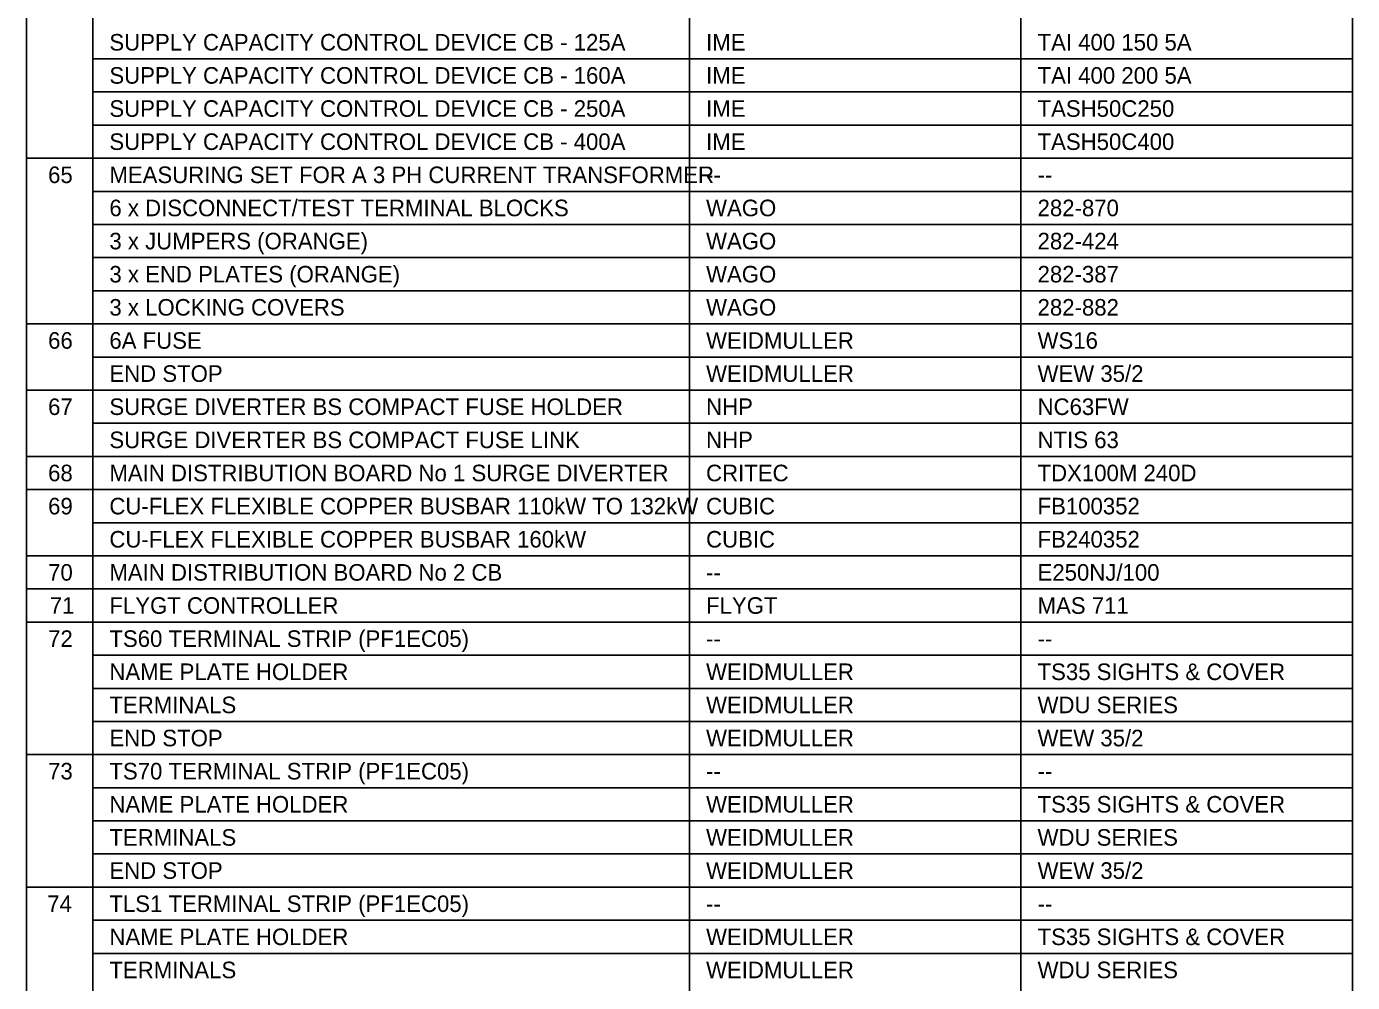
# Model space of a CAD drawing. Extents: x 841 to 1682, y 0 to 594.
# Drawn here: x 1340 to 1540, y 155.6 to 299.9 of the extents above; entities that cross this region are included whole.
import ezdxf

# ---------------------------------------------------------------- set-up
doc = ezdxf.new("R2010")
doc.units = 0
doc.layers.add('Level 1', color=7, linetype='Continuous')

msp = doc.modelspace()

# ---------------------------------------------------------------- linework, layer by layer
at = {"layer": 'Level 1'}
for p, q in [((1340, 568.5), (1340, 75)), ((1540, 75), (1540, 568.5)), ((1350, 558.75), (1350, 75)), ((1440, 558.75), (1440, 75)), ((1490, 558.75), (1490, 75)), ((1350, 295), (1540, 295)), ((1350, 290), (1540, 290)), ((1350, 285), (1540, 285)), ((1340, 280), (1540, 280)), ((1350, 275), (1540, 275)), ((1350, 270), (1540, 270)), ((1350, 265), (1540, 265)), ((1350, 260), (1540, 260)), ((1340, 255), (1540, 255)), ((1350, 250), (1540, 250)), ((1340, 245), (1540, 245)), ((1350, 240), (1540, 240)), ((1340, 235), (1540, 235)), ((1340, 230), (1540, 230)), ((1350, 225), (1540, 225)), ((1340, 220), (1540, 220)), ((1340, 215), (1540, 215)), ((1340, 210), (1540, 210)), ((1350, 205), (1540, 205)), ((1350, 200), (1540, 200)), ((1350, 195), (1540, 195)), ((1340, 190), (1540, 190)), ((1350, 185), (1540, 185)), ((1350, 180), (1540, 180)), ((1350, 175), (1540, 175)), ((1340, 170), (1540, 170)), ((1350, 165), (1540, 165)), ((1350, 160), (1540, 160))]:
    msp.add_line(p, q, dxfattribs=at)

# ---------------------------------------------------------------- texts
for s, p in [('SUPPLY CAPACITY CONTROL DEVICE CB - 125A', (1352.5, 296.25)), ('IME', (1442.5, 296.25)), ('TAI 400 150 5A', (1492.5, 296.25)), ('SUPPLY CAPACITY CONTROL DEVICE CB - 160A', (1352.5, 291.25)), ('IME', (1442.5, 291.25)), ('TAI 400 200 5A', (1492.5, 291.25)), ('SUPPLY CAPACITY CONTROL DEVICE CB - 250A', (1352.5, 286.25)), ('IME', (1442.5, 286.25)), ('TASH50C250', (1492.5, 286.25)), ('SUPPLY CAPACITY CONTROL DEVICE CB - 400A', (1352.5, 281.25)), ('IME', (1442.5, 281.25)), ('TASH50C400', (1492.5, 281.25)), ('65', (1343.257, 276.25)), ('MEASURING SET FOR A 3 PH CURRENT TRANSFORMER', (1352.5, 276.25)), ('--', (1442.5, 276.25)), ('--', (1492.5, 276.25)), ('6 x DISCONNECT/TEST TERMINAL BLOCKS', (1352.5, 271.25)), ('WAGO', (1442.5, 271.25)), ('282-870', (1492.5, 271.25)), ('3 x JUMPERS (ORANGE)', (1352.5, 266.25)), ('WAGO', (1442.5, 266.25)), ('282-424', (1492.5, 266.25)), ('3 x END PLATES (ORANGE)', (1352.5, 261.25)), ('WAGO', (1442.5, 261.25)), ('282-387', (1492.5, 261.25)), ('3 x LOCKING COVERS', (1352.5, 256.25)), ('WAGO', (1442.5, 256.25)), ('282-882', (1492.5, 256.25)), ('66', (1343.257, 251.25)), ('6A FUSE', (1352.5, 251.25)), ('WEIDMULLER', (1442.5, 251.25)), ('WS16', (1492.5, 251.25)), ('END STOP', (1352.5, 246.25)), ('WEIDMULLER', (1442.5, 246.25)), ('WEW 35/2', (1492.5, 246.25)), ('67', (1343.257, 241.25)), ('SURGE DIVERTER BS COMPACT FUSE HOLDER', (1352.5, 241.25)), ('NHP', (1442.5, 241.25)), ('NC63FW', (1492.5, 241.25)), ('SURGE DIVERTER BS COMPACT FUSE LINK', (1352.5, 236.25)), ('NHP', (1442.5, 236.25)), ('NTIS 63', (1492.5, 236.25)), ('68', (1343.257, 231.25)), ('MAIN DISTRIBUTION BOARD No 1 SURGE DIVERTER', (1352.5, 231.25)), ('CRITEC', (1442.5, 231.25)), ('TDX100M 240D', (1492.5, 231.25)), ('69', (1343.257, 226.25)), ('CU-FLEX FLEXIBLE COPPER BUSBAR 110kW TO 132kW', (1352.5, 226.25)), ('CUBIC', (1442.5, 226.25)), ('FB100352', (1492.5, 226.25)), ('CU-FLEX FLEXIBLE COPPER BUSBAR 160kW', (1352.5, 221.25)), ('CUBIC', (1442.5, 221.25)), ('FB240352', (1492.5, 221.25)), ('70', (1343.257, 216.25)), ('MAIN DISTRIBUTION BOARD No 2 CB', (1352.5, 216.25)), ('E250NJ/100', (1492.5, 216.25)), ('--', (1442.5, 216.25)), ('71', (1343.506, 211.25)), ('FLYGT CONTROLLER', (1352.5, 211.25)), ('FLYGT', (1442.5, 211.25)), ('MAS 711', (1492.5, 211.25)), ('72', (1343.257, 206.25)), ('TS60 TERMINAL STRIP (PF1EC05)', (1352.5, 206.25)), ('--', (1442.5, 206.25)), ('--', (1492.5, 206.25)), ('NAME PLATE HOLDER', (1352.5, 201.25)), ('WEIDMULLER', (1442.5, 201.25)), ('TS35 SIGHTS & COVER', (1492.5, 201.25)), ('TERMINALS', (1352.5, 196.25)), ('WEIDMULLER', (1442.5, 196.25)), ('WDU SERIES', (1492.5, 196.25)), ('END STOP', (1352.5, 191.25)), ('WEIDMULLER', (1442.5, 191.25)), ('WEW 35/2', (1492.5, 191.25)), ('73', (1343.257, 186.25)), ('TS70 TERMINAL STRIP (PF1EC05)', (1352.5, 186.25)), ('--', (1442.5, 186.25)), ('--', (1492.5, 186.25)), ('NAME PLATE HOLDER', (1352.5, 181.25)), ('WEIDMULLER', (1442.5, 181.25)), ('TS35 SIGHTS & COVER', (1492.5, 181.25)), ('TERMINALS', (1352.5, 176.25)), ('WEIDMULLER', (1442.5, 176.25)), ('WDU SERIES', (1492.5, 176.25)), ('END STOP', (1352.5, 171.25)), ('WEIDMULLER', (1442.5, 171.25)), ('WEW 35/2', (1492.5, 171.25)), ('74', (1343.132, 166.25)), ('TLS1 TERMINAL STRIP (PF1EC05)', (1352.5, 166.25)), ('--', (1442.5, 166.25)), ('--', (1492.5, 166.25)), ('NAME PLATE HOLDER', (1352.5, 161.25)), ('WEIDMULLER', (1442.5, 161.25)), ('TS35 SIGHTS & COVER', (1492.5, 161.25)), ('TERMINALS', (1352.5, 156.25)), ('WEIDMULLER', (1442.5, 156.25)), ('WDU SERIES', (1492.5, 156.25))]:
    msp.add_text(s, height=2.5, dxfattribs=at).set_placement(p)

doc.saveas('drawing.dxf')
